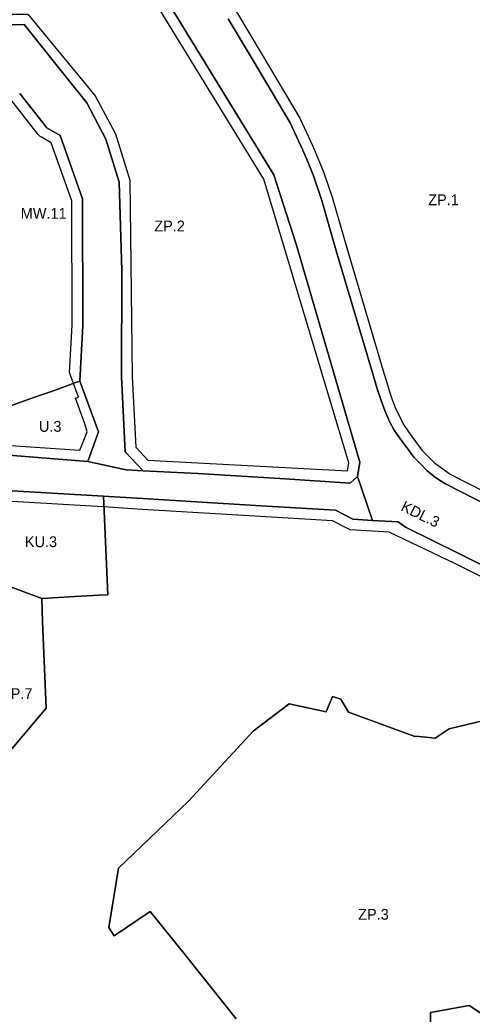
# Model space of a CAD drawing. Extents: x 7421913 to 7423341, y 5550123 to 5551175.
# Drawn here: x 7422618.9 to 7422827.7, y 5550484.1 to 5550943.3 of the extents above; entities that cross this region are included whole.
import ezdxf

# ---------------------------------------------------------------- set-up
doc = ezdxf.new("R2010")
doc.units = 0
for name, color, linetype in [('linie_rozgraniczajace', 7, 'Continuous'), ('linie_zabudowy_nieprzekraczalne', 7, 'Continuous'), ('oznaczenia_przeznaczen', 7, 'Continuous')]:
    doc.layers.add(name, color=color, linetype=linetype)

msp = doc.modelspace()

# ---------------------------------------------------------------- linework, layer by layer
at = {"layer": 'linie_rozgraniczajace'}
for points in [[(7422660.2, 5550995.93), (7422736.14, 5550871.82), (7422746.45, 5550839.81), (7422775.86, 5550739.06), (7422774.83, 5550732.45), (7422771.39, 5550729.31), (7422738.92, 5550731.51), (7422701.03, 5550733.87), (7422675.81, 5550735.06), (7422667.52, 5550743.81), (7422665.8, 5550778.51), (7422665.93, 5550827.56), (7422664.73, 5550868.38), (7422658.65, 5550888.31), (7422649.82, 5550905.1), (7422641.09, 5550916.01), (7422620.84, 5550941.29), (7422603.26, 5550941.04), (7422579.8, 5550936.89), (7422573.93, 5550935.06), (7422555.21, 5550929.23), (7422550.98, 5550956.47)], [(7422859.96, 5550677.58), (7422821.9, 5550696.63), (7422796.94, 5550709.04), (7422793.57, 5550711.53), (7422781.79, 5550712.09), (7422774.83, 5550732.45), (7422775.86, 5550739.06), (7422746.45, 5550839.81), (7422736.14, 5550871.82), (7422660.2, 5550995.93)], [(7422603.26, 5550941.04), (7422620.84, 5550941.29), (7422641.09, 5550916.01), (7422649.82, 5550905.1), (7422658.65, 5550888.31), (7422664.73, 5550868.38), (7422665.93, 5550827.56), (7422665.8, 5550778.51), (7422667.52, 5550743.81), (7422675.81, 5550735.06), (7422667.94, 5550735.43), (7422650.24, 5550739.36), (7422655.25, 5550753.04), (7422646.53, 5550776.5), (7422648, 5550802.13), (7422647.84, 5550860.66), (7422637.53, 5550890.01), (7422631.31, 5550893.52), (7422618.9, 5550909.29)], [(7422715.07, 5550943.89), (7422726.56, 5550924.6), (7422743.68, 5550895.76), (7422746.57, 5550889.55), (7422749.61, 5550883.12), (7422751.99, 5550877.48), (7422754.45, 5550871.34), (7422758.35, 5550859.85), (7422765, 5550836.72), (7422781.91, 5550779.77), (7422783.94, 5550772.98), (7422785.67, 5550767.49), (7422787.62, 5550762.43), (7422789.79, 5550757.52), (7422791.74, 5550753.83), (7422794.63, 5550749.64), (7422797.81, 5550745.3), (7422800.78, 5550741.33), (7422803.74, 5550738.44), (7422806.99, 5550735.04), (7422810.82, 5550731.93), (7422815.08, 5550729.19), (7422917.1, 5550677.04)], [(7422917.1, 5550677.04), (7422815.08, 5550729.19), (7422810.82, 5550731.93), (7422806.99, 5550735.04), (7422803.74, 5550738.44), (7422800.78, 5550741.33), (7422797.81, 5550745.3), (7422794.63, 5550749.64), (7422791.74, 5550753.83), (7422789.79, 5550757.52), (7422787.62, 5550762.43), (7422785.67, 5550767.49), (7422783.94, 5550772.98), (7422781.91, 5550779.77), (7422765, 5550836.72), (7422758.35, 5550859.85), (7422754.45, 5550871.34), (7422751.99, 5550877.48), (7422749.61, 5550883.12), (7422746.57, 5550889.55), (7422743.68, 5550895.76), (7422726.56, 5550924.6), (7422715.07, 5550943.89)], [(7422618.9, 5550909.29), (7422631.31, 5550893.52), (7422637.53, 5550890.01), (7422647.84, 5550860.66), (7422648, 5550802.13), (7422646.53, 5550776.5), (7422643.86, 5550775.53), (7422639.81, 5550774.05), (7422633.46, 5550771.71), (7422626.65, 5550769.34), (7422610.77, 5550763.7)], [(7422609.82, 5550742.52), (7422650.24, 5550739.36), (7422667.94, 5550735.43), (7422675.81, 5550735.06), (7422701.03, 5550733.87), (7422738.92, 5550731.51), (7422771.39, 5550729.31), (7422774.83, 5550732.45), (7422781.79, 5550712.09), (7422772.68, 5550712.64), (7422764.65, 5550716.87), (7422727.72, 5550719.03), (7422675.73, 5550722.2), (7422660.02, 5550723.17), (7422657.58, 5550723.32), (7422610.06, 5550726.12)], [(7422563.21, 5550461.08), (7422568.23, 5550485.99), (7422578.06, 5550536.87), (7422584.47, 5550571.85), (7422588.7, 5550571.2), (7422595.34, 5550570.19), (7422605.22, 5550594.9), (7422631.08, 5550625.32), (7422629.43, 5550665.34), (7422628.99, 5550676.11), (7422641.87, 5550676.81), (7422655.16, 5550677.53), (7422659.5, 5550677.77), (7422657.58, 5550723.32), (7422660.02, 5550723.17), (7422675.73, 5550722.2), (7422727.72, 5550719.03), (7422764.65, 5550716.87), (7422772.68, 5550712.64), (7422781.79, 5550712.09), (7422793.57, 5550711.53), (7422796.94, 5550709.04), (7422821.9, 5550696.63), (7422859.96, 5550677.58)], [(7422833.14, 5550619.75), (7422817.07, 5550615.79), (7422810.72, 5550611.48), (7422801.78, 5550612.47), (7422801.31, 5550612.25), (7422770.62, 5550623.55), (7422767.16, 5550629.5), (7422763.18, 5550630.74), (7422760.31, 5550623.74), (7422743.25, 5550627.36), (7422726.63, 5550614.77), (7422696.74, 5550582.39), (7422664.46, 5550551.55), (7422660.06, 5550524.02), (7422662.5, 5550520.24), (7422679.05, 5550531.46), (7422695.28, 5550511.38), (7422718.75, 5550481.94)], [(7422718.75, 5550481.94), (7422695.28, 5550511.38), (7422679.05, 5550531.46), (7422662.5, 5550520.24), (7422660.06, 5550524.02), (7422664.46, 5550551.55), (7422696.74, 5550582.39), (7422726.63, 5550614.77), (7422743.25, 5550627.36), (7422760.31, 5550623.74), (7422763.18, 5550630.74), (7422767.16, 5550629.5), (7422770.62, 5550623.55), (7422801.31, 5550612.25), (7422801.78, 5550612.47), (7422810.72, 5550611.48), (7422817.07, 5550615.79), (7422833.14, 5550619.75)], [(7422808.82, 5550461.16), (7422808.51, 5550484.83), (7422826.33, 5550488), (7422833.57, 5550483.2)], [(7422833.57, 5550483.2), (7422826.33, 5550488), (7422808.51, 5550484.83), (7422808.82, 5550461.16)]]:
    msp.add_lwpolyline(points, dxfattribs=at)
for points in [[(7422650.24, 5550739.36), (7422609.82, 5550742.52), (7422610.77, 5550763.7), (7422626.65, 5550769.34), (7422633.46, 5550771.71), (7422639.81, 5550774.05), (7422643.86, 5550775.53), (7422646.53, 5550776.5), (7422655.25, 5550753.04)], [(7422657.58, 5550723.32), (7422659.5, 5550677.77), (7422655.16, 5550677.53), (7422641.87, 5550676.81), (7422628.99, 5550676.11), (7422613.4, 5550681.83), (7422613.12, 5550681.94), (7422598.57, 5550687.28), (7422595.2, 5550721.24), (7422592.25, 5550724.59), (7422610.06, 5550726.12)], [(7422628.99, 5550676.11), (7422629.43, 5550665.34), (7422631.08, 5550625.32), (7422605.22, 5550594.9), (7422595.34, 5550570.19), (7422588.7, 5550571.2), (7422584.47, 5550571.85), (7422551.74, 5550577), (7422552.34, 5550579.58), (7422541.04, 5550581.37), (7422545.56, 5550587.53), (7422593.68, 5550581.23), (7422606.35, 5550625.07), (7422605.02, 5550625.06), (7422607.4, 5550635.57), (7422611.31, 5550658.75), (7422612.13, 5550664.64), (7422612.8, 5550670.22), (7422613.12, 5550681.94), (7422613.4, 5550681.83)]]:
    msp.add_lwpolyline(points, close=True, dxfattribs=at)
at = {"layer": 'linie_zabudowy_nieprzekraczalne'}
for points in [[(7422907.16, 5551048.18), (7422695.05, 5551002.61), (7422707.77, 5550969.27), (7422710.26, 5550963.4), (7422719.42, 5550946.36), (7422730.85, 5550927.16), (7422748.22, 5550897.87), (7422754.21, 5550885.07), (7422759.09, 5550873.19), (7422763.09, 5550861.46), (7422769.8, 5550838.12), (7422786.71, 5550781.2), (7422790.39, 5550769.14), (7422792.25, 5550764.34), (7422796.02, 5550756.43), (7422798.71, 5550752.54), (7422804.55, 5550744.63), (7422810.38, 5550738.73), (7422817.58, 5550733.53), (7422915.07, 5550683.69)], [(7422678.04, 5550739.96), (7422770.16, 5550734.96), (7422770.75, 5550738.73), (7422731.56, 5550869.71), (7422657.74, 5550990.37), (7422561, 5550973.05), (7422525.2, 5550961.89), (7422483.76, 5550946.38)], [(7422554.43, 5550934.23), (7422578.93, 5550941.81), (7422603.19, 5550946.04), (7422622.55, 5550945.99), (7422653.72, 5550908.22), (7422663.08, 5550890.64), (7422669.65, 5550869.25), (7422670.8, 5550778.63), (7422672.43, 5550745.91), (7422678.04, 5550739.96)], [(7422588.18, 5550746.17), (7422610.02, 5550747.01), (7422646.67, 5550744.54), (7422649.92, 5550753.03), (7422648.89, 5550756.7), (7422644.55, 5550768.66), (7422646.02, 5550769.08), (7422641.76, 5550780.48), (7422643, 5550802.27), (7422642.84, 5550859.8), (7422633.44, 5550886.58), (7422628.85, 5550889.17), (7422628.81, 5550889.19), (7422628.53, 5550889.36), (7422628.27, 5550889.55), (7422628.01, 5550889.76), (7422627.77, 5550889.98), (7422627.55, 5550890.22), (7422627.38, 5550890.43), (7422615.14, 5550905.98), (7422609.84, 5550911.38), (7422603.85, 5550917.48), (7422599.24, 5550919.87), (7422590.8, 5550920.67)], [(7422857.71, 5550673.12), (7422819.67, 5550692.16), (7422789.49, 5550706.74), (7422771.39, 5550707.81), (7422763.28, 5550711.94), (7422727.43, 5550714.04), (7422727.42, 5550714.04), (7422675.43, 5550717.21), (7422675.42, 5550717.21), (7422659.71, 5550718.18), (7422657.28, 5550718.33), (7422610.13, 5550721.11)]]:
    msp.add_lwpolyline(points, dxfattribs=at)

# ---------------------------------------------------------------- texts
at = {"layer": 'oznaczenia_przeznaczen'}
for s, p in [('ZP.1', (7422807.44, 5550857.75)), ('MW.11', (7422619.33, 5550851.49)), ('ZP.2', (7422680.97, 5550845.64)), ('U.3', (7422627.73, 5550753.06)), ('KU.3', (7422621.24, 5550699.78)), ('ZP.7', (7422610.63, 5550629.59)), ('ZP.3', (7422775.1, 5550527.65))]:
    msp.add_text(s, height=5, dxfattribs=at).set_placement(p)
msp.add_text('KDL.3', height=5, rotation=333.7459, dxfattribs=at).set_placement((7422794.42, 5550716.89))

doc.saveas('drawing.dxf')
